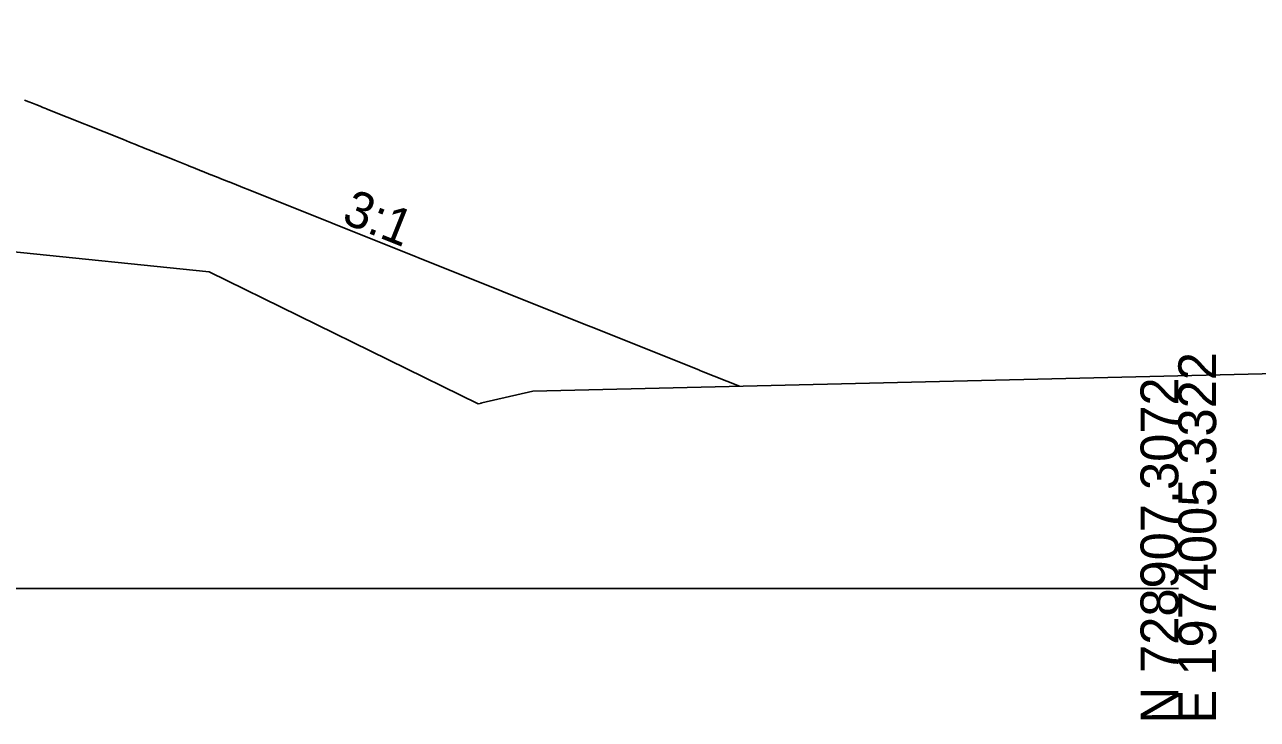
# Model space of a CAD drawing. Extents: x -26 to 630, y -39 to 9098.
# Drawn here: x 364.6 to 455.8, y 4490.3 to 4541.7 of the extents above; entities that cross this region are included whole.
import ezdxf

# ---------------------------------------------------------------- set-up
doc = ezdxf.new("R2010")
doc.units = 0
for name, color, linetype in [('Default', 7, 'Continuous'), ('DTM_X_GROUND', 7, 'Continuous'), ('XS_CELL', 7, 'Continuous'), ('XS_P_GROUND', 7, 'Continuous'), ('XS_P_TX_FS_BS', 7, 'Continuous')]:
    doc.layers.add(name, color=color, linetype=linetype)

msp = doc.modelspace()

# ---------------------------------------------------------------- linework, layer by layer
at = {"layer": 'DTM_X_GROUND'}
msp.add_lwpolyline([(273.785, 4541.709), (282.717, 4539.976), (289.49, 4538.601), (302.18, 4535.761), (307.933, 4534.479), (309.869, 4534.062), (319.934, 4536.719), (332.102, 4532.936), (358.076, 4520.793), (363.315, 4524.958), (378.264, 4523.408), (398.158, 4513.652), (398.315, 4513.689), (398.317, 4513.689), (398.345, 4513.695), (398.375, 4513.702), (398.407, 4513.71), (398.441, 4513.717), (402.222, 4514.589), (515.384, 4517.29)], dxfattribs=at)
at = {"layer": 'XS_CELL'}
msp.add_line((100, 4500), (450, 4500), dxfattribs=at)
at = {"layer": 'XS_P_GROUND'}
for points in [[(364.593, 4536.125), (364.905, 4536), (364.912, 4535.997)], [(364.912, 4535.997), (365.176, 4535.892), (365.182, 4535.889)], [(365.182, 4535.889), (365.409, 4535.799), (365.414, 4535.797)], [(365.414, 4535.797), (365.61, 4535.718), (365.615, 4535.716)], [(365.615, 4535.716), (365.787, 4535.647), (365.791, 4535.646)], [(365.791, 4535.646), (365.942, 4535.585), (365.946, 4535.584)], [(365.946, 4535.584), (366.081, 4535.53), (366.084, 4535.529)], [(366.084, 4535.529), (366.204, 4535.48), (366.208, 4535.479)], [(366.208, 4535.479), (366.316, 4535.436), (366.319, 4535.435)], [(366.319, 4535.435), (371.904, 4533.2), (372.344, 4533.025), (372.875, 4532.812), (373.022, 4532.753), (373.292, 4532.645), (373.396, 4532.604), (374.028, 4532.351), (374.374, 4532.212), (374.482, 4532.169), (374.487, 4532.167), (375.032, 4531.949), (375.048, 4531.943), (375.704, 4531.681), (375.721, 4531.674), (376.69, 4531.286), (376.719, 4531.275), (377.058, 4531.139), (377.063, 4531.137), (377.715, 4530.876), (377.732, 4530.869), (378.384, 4530.609), (378.401, 4530.602), (379.052, 4530.341), (379.068, 4530.335), (379.719, 4530.075), (379.735, 4530.068), (380.268, 4529.855), (380.281, 4529.85), (380.574, 4529.733), (380.578, 4529.731), (380.86, 4529.618), (380.863, 4529.617), (381.133, 4529.509), (381.137, 4529.507), (406.146, 4519.504), (406.521, 4519.354), (414.501, 4516.162), (414.577, 4516.131), (414.703, 4516.081), (417.521, 4514.954)]]:
    msp.add_lwpolyline(points, dxfattribs=at)

# ---------------------------------------------------------------- texts
at = {"layer": 'Default'}
for height, p in [(0.12, (417.482, 4514.894)), (0.12, (417.482, 4514.894)), (0.001, (417.521, 4514.953))]:
    msp.add_text('X', height=height, dxfattribs=at).set_placement(p)
at = {"layer": 'XS_CELL'}
for s, p in [('E 1974005.3322', (452.8, 4490)), ('N 728907.3072', (450, 4490))]:
    msp.add_text(s, height=2.8, rotation=90, dxfattribs=at).set_placement(p)
at = {"layer": 'XS_P_TX_FS_BS'}
msp.add_text('3:1', height=2.7, rotation=338.19859, dxfattribs=at).set_placement((387.969, 4527.098))

doc.saveas('drawing.dxf')
